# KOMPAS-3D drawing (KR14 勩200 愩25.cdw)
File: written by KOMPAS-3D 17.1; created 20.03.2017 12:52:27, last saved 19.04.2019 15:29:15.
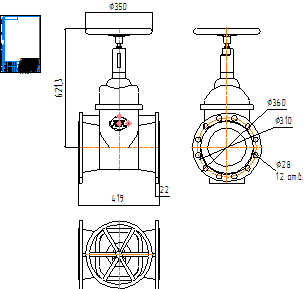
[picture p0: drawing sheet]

Sheet 1: A4, portrait

Title block, sheet 1: name: KR14 Ду200 Ру25; material: Внимание! Данный продукт является объектом авторского права ООО «Торговый Дом АДЛ». / Запрещается изменение, копирование, распространение / (в том числе путем копирования на другие сайты и ресурсы в Интернете) / или любое иное использование информации и объектов без предварительного / согласия правообладателя (ООО «Торговый Дом АДЛ»).; mass: 508; sheets: 1; organisation: ООО "Торговый дом АДЛ"; sheet format: A4; stored path: C:\Users\kka\KOMPAS_Work\!Trash\Задвижки ГРАНАР с приводами\KR14 Ду350 Ру16.cdw

Views: Вид 1, Проекционный вид 2, Проекционный вид 3
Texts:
  Klimkovich
  ADL
Dimensions and other numbers on the sheet: 350; 621,3; 419; 360; 310; 28; 12 отв.; 22; 1:1; 1; 508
